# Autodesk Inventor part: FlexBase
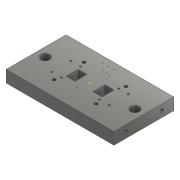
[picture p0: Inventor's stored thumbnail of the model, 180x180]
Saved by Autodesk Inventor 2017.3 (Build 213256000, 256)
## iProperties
Part Number: FlexBase
Material: ステンレス鋼
Document SubType Name: モデリング
Designer: kyushu-hep
Density: 8 g/cm^3
Appearance: 半つや出し
Sheet Metal Rule: Default
Mass: 5352.02 g
Surface Area: 367.335 cm^2
Volume: 277.307 cm^3
Author: kyushu-hep
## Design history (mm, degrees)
sketch "スケッチ1"
  geometry: L1 (-126, 0)-(126, 0) reference; L2 (0, -70)-(0, 70) reference; L3 (90, -50)-(-90, -50); L4 (-90, -50)-(-90, 50); L5 (-90, 50)-(90, 50); L6 (90, 50)-(90, -50); L7 (90, -50)-(-90, 50); L8 (-90, -50)-(90, 50); 1 further point
  constraints: 12 end point, 2 midpoint, 2 parallel, 1 horizontal, 1 perpendicular
  dimensions: "d0" = 180 distance of L4.end L5.end; "d1" = 100 distance of L3.end L4.end
extrude "押し出し1" new body sketch "スケッチ1" distance "d2" = 20; taper "d3" = 0 deg
sketch "スケッチ18"
  geometry: L1 (-90, 50)-(-90, -50) reference; L2 (-15, -10)-(-30, -10); L3 (-30, -10)-(-30, 10); L4 (-30, 10)-(-15, 10); L5 (-15, 10)-(-15, -10); L6 (-15, -10)-(-30, 10); L7 (-30, -10)-(-15, 10); L8 (90, -50)-(90, 50) reference; L9 (15, -10)-(30, -10); L10 (30, -10)-(30, 10); L11 (30, 10)-(15, 10); L12 (15, 10)-(15, -10); L13 (15, -10)-(30, 10); L14 (30, -10)-(15, 10); L15 (-90, -50)-(90, -50) reference; 3 further points
  constraints: 24 end point, 4 midpoint, 4 parallel, 2 equal length, 2 horizontal, 2 perpendicular, 1 collinear
  dimensions: "d108" = 15 distance from line of point (0, 0) L5; "d109" = 20 distance of L4.end L2.start; "d135" = 10 distance from line of point (0, 0) L2; "d151" = 15 distance of L2.start L2.end; "d152" = 15 distance from line of L12 point (0, 0)
extrude "押し出し15" cut sketch "スケッチ18" distance "d111" = 30; taper "d112" = 0 deg
sketch "スケッチ22"
  geometry: 1 further point
sketch "スケッチ23"
  geometry: C1 r 7.5 at (-75, 0); C2 r 7.5 at (75, 0); 1 further point
  constraints: 2 centre point
  dimensions: "d181" = 15 diameter of C1; "d184" = 15 diameter of C2; "d200" = 0 vertical distance of point (0, 0) C1.centre; "d201" = 0 vertical distance of C2.centre point (0, 0); "d204" = 75 distance of point (0, 0) C1.centre; "d205" = 75 distance of C2.centre point (0, 0)
sketch "スケッチ24"
  geometry: C1 r 2.5 at (-35, 25); C2 r 2.5 at (35, 25); C3 r 2.5 at (-35, -25); C4 r 2.5 at (35, -25); 2 further points
  constraints: 4 centre point, 1 coincident
  dimensions: "d159" = 5 diameter of C1; "d160" = 25 vertical distance of C1.centre point (0, 0); "d161" = 35 horizontal distance of C1.centre point (0, 0); "d162" = 5 diameter of C2; "d163" = 35 horizontal distance of point (0, 0) C2.centre; "d164" = 25 vertical distance of C2.centre point (0, 0); "d165" = 5 diameter of C3; "d166" = 25 vertical distance of point (0, 0) C3.centre; "d167" = 35 horizontal distance of point (0, 0) C3.centre; "d168" = 5 diameter of C4; "d169" = 25 vertical distance of point (0, 0) C4.centre; "d170" = 35 horizontal distance of point (0, 0) C4.centre
extrude "押し出し19" cut sketch "スケッチ24" distance "d171" = 20; taper "d172" = 0 deg
feature "ねじ4" dims "d173" = 10, "d174" = 0
feature "ねじ5" dims "d175" = 10, "d176" = 0
feature "ねじ6" dims "d177" = 10, "d178" = 0
feature "ねじ7" dims "d179" = 10, "d180" = 0
sketch "スケッチ25"
  geometry: L1 (20, 20)-(-20, 20); L2 (-20, 20)-(-20, -20); L3 (-20, -20)-(20, -20); L4 (20, -20)-(20, 20); L5 (20, 20)-(-20, -20); L6 (-20, 20)-(20, -20); C1 r 1.5 at (-48, -16); C2 r 1.5 at (-48, 16); C3 r 1.5 at (-32, -16); C4 r 1.5 at (-32, 16); C5 r 1.5 at (-16, -16); C6 r 1.5 at (-16, 16); C7 r 1.5 at (0, -16); C8 r 1.5 at (0, 16); C9 r 1.5 at (16, -16); C10 r 1.5 at (16, 16); C11 r 1.5 at (32, -16); C12 r 1.5 at (32, 16); C13 r 1.5 at (48, -16); C14 r 1.5 at (48, 16); 2 further points
  constraints: 14 centre point, 12 end point, 2 horizontal, 2 midpoint, 2 parallel, 1 perpendicular, 1 vertical, 26 other
  dimensions: "d191" = 3 diameter of C1; "d192" = 48 horizontal distance of point (0, 0) C1.centre; "d193" = 16 vertical distance of point (0, 0) C1.centre; "d194" = 40 distance of L3.end L2.end; "d195" = 40 distance of L2.end L1.end; "d196" = 32 distance of C1.centre C2.centre; "d197" = 16 distance of C1.centre C3.centre
extrude "押し出し21" cut sketch "スケッチ25" distance "d198" = 20; taper "d199" = 0 deg
extrude "押し出し22" cut sketch "スケッチ23" distance "d202" = 10; taper "d203" = 0 deg
sketch "スケッチ26"
  geometry: C1 r 2.5 at (-10, 20); C2 r 2.5 at (-10, 80); 1 further point
  constraints: 2 centre point
  dimensions: "d206" = 5 diameter of C1; "d207" = 30 vertical distance of C1.centre point (0, 50); "d208" = 5 diameter of C2; "d209" = 30 vertical distance of C2.centre point (0, 50); "d210" = 10 horizontal distance of C1.centre point (0, 50); "d211" = 10 horizontal distance of C2.centre point (0, 50)
extrude "押し出し23" cut sketch "スケッチ26" distance "d212" = 10; taper "d213" = 0 deg
feature "ねじ8" dims "d214" = 10, "d215" = 0
feature "ねじ9" dims "d216" = 10, "d217" = 0
sketch "スケッチ27"
  geometry: C1 r 2.5 at (10, 80); C2 r 2.5 at (10, 20); 1 further point
  constraints: 2 centre point
  dimensions: "d218" = 5 diameter of C1; "d219" = 5 diameter of C2; "d220" = 30 vertical distance of point (0, 50) C1.centre; "d221" = 30 vertical distance of point (0, 50) C2.centre; "d222" = 10 horizontal distance of point (0, 50) C1.centre; "d223" = 10 horizontal distance of point (0, 50) C2.centre
extrude "押し出し24" cut sketch "スケッチ27" distance "d224" = 10; taper "d225" = 0 deg
feature "ねじ10" dims "d226" = 10, "d227" = 0
feature "ねじ11" dims "d228" = 10, "d229" = 0
sketch "スケッチ12"
  geometry: L1 (-90, 50)-(-90, -50) reference; L2 (-90, -50)-(90, -50) reference; C1 r 0.5 at (-5.05, 27.5); C2 r 0.5 at (5.05, 27.5); C3 r 0.5 at (0, 27.5); C4 r 0.5 at (0, 39); C5 r 0.5 at (-9, 39); C6 r 0.5 at (-18, 39); C7 r 0.5 at (-5.05, -16.5); C8 r 0.5 at (5.05, -16.5); 1 further point
  constraints: 8 centre point
  dimensions: "d66" = 1 diameter of C1; "d67" = 1 diameter of C2; "d130" = 10.1 distance of C2.centre C1.centre; "d133" = 27.5 vertical distance of point (0, 0) C2.centre; "d134" = 5.05 horizontal distance of C1.centre point (0, 0); "d230" = 10.1 distance of C2.centre C1.centre; "d231" = 1 diameter of C3; "d232" = 1 diameter of C4; "d233" = 11.5 distance of C4.centre C3.centre; "d234" = 1 diameter of C5; "d235" = 1 diameter of C6; "d236" = 9 distance of C4.centre C5.centre; "d237" = 5.05 distance of C1.centre C3.centre; "d238" = 9 distance of C5.centre C6.centre; "d241" = 1 diameter of C7; "d242" = 44 distance of C7.centre C1.centre; "d243" = 1 diameter of C8; "d246" = 44 distance of C2.centre C8.centre
extrude "押し出し26" cut sketch "スケッチ12" distance "d244" = 10; taper "d245" = 0 deg
node "ソリッド1"
other parameters: "Thickness" = 0.5, "Kファクター" = 4.4, "BendRadius" = 0.5 (= Thickness), "BendReliefWidth" = 0.5 (= Thickness), "BendReliefDepth" = 0.25 (= 0.5 x Thickness), "CornerReliefSize" = 2 (= 4 x Thickness), "SeamGap" = 0.01, "MinimumRemnant" = 1 (= 2 x Thickness), "TransitionRadius" = 0.5 (= BendRadius), "JacobiRadiusSize" = 0.5 (= Thickness), "GapSize" = 0.5 (= Thickness)
